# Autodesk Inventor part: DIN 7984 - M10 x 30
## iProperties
Created: 2006-02
Part Number: DIN 7984 - M10 x 30
Material: Steel, Mild
Description: Cylinder Head Cap Screw
Document SubType Name: Modeling
Standard: DIN 7984
Designer: Andy Moles
Standards Organization: DIN
Language: en-US
Size Designation: M10 x 30
Categories: <MemberInstance><Categories><Category DisplayName="Fasteners" InternalName="e4da775c-781d-43d5-af7c-5136215cf5a6" Mnemonic="FSTN"><Category DisplayName="Bolts"
Density: 1 g/cm^3
Author: Andy Moles
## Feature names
1. Body [Revolution]
2. Slot [Extrusion]
3. Fillet1
4. Chamfer1
